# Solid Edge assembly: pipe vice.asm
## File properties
Author: CADCIM
Template: Iso Assembly.asm
Last saved by: CADCIM
Revision: 1
Application: Solid Edge
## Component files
base.par
Screw.par
moveable jaw.par
handle.par
handle screw.par
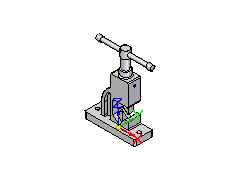
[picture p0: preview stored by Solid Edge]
